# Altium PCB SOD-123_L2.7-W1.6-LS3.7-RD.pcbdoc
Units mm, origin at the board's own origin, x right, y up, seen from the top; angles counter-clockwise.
Board outline 16.88 x 14.7 mm, 2 copper layers (Top Layer, Bottom Layer), stack 0 mm thick; 1 components, 0 nets, 2 pads, 0 vias.
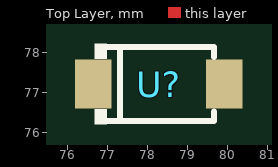
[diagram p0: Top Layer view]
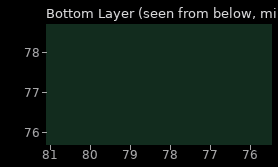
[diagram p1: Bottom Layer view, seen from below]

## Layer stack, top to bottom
Top Layer: signal copper (thickness not stored)
Bottom Layer: signal copper (thickness not stored)

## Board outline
86.73,69.85 69.85,69.85 69.85,84.555 86.73,84.555

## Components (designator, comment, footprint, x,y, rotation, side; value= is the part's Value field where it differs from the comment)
U? "" SOD-123_L2.7-W1.6-LS3.7-RD 78.29,77.202 r0 top

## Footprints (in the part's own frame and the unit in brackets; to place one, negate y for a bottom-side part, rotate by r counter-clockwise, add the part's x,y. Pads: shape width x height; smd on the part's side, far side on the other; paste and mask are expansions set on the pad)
SOD-123_L2.7-W1.6-LS3.7-RD [mm]
  rect 0.91x1.22 smd: 1(-1.635,0) 2(1.635,0)
  silkscreen extent -1.6,-1 1.38,1

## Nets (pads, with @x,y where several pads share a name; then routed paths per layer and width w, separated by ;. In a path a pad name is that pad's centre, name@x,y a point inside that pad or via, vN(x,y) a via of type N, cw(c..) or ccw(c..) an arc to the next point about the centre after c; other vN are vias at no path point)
pads on no net: U?.1 U?.2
